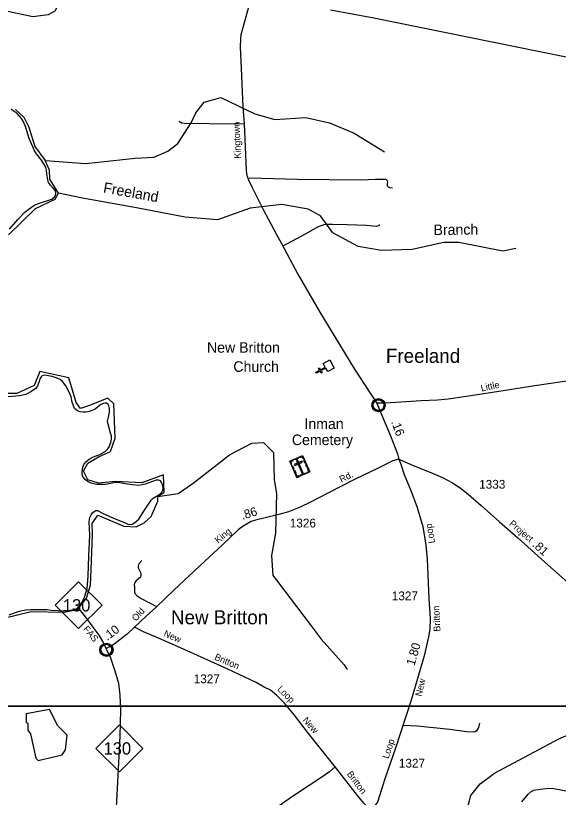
# Model space of a CAD drawing. Extents: x 2104537 to 2336408, y 34176 to 229611.
# Drawn here: x 2135938 to 2143655, y 123300 to 134413 of the extents above; entities that cross this region are included whole.
import ezdxf

# ---------------------------------------------------------------- set-up
doc = ezdxf.new("R2010")
doc.units = 0
for name, color, linetype in [('Exist Boundary Political CountyLine', 7, 'Continuous'), ('Exist Civil Demographics Community CELL', 7, 'Continuous'), ('Exist Civil Demographics Community Label', 7, 'Continuous'), ('Exist Cultural Cemetery CELL', 7, 'Continuous'), ('Exist Cultural Cemetery Label', 7, 'Continuous'), ('Exist Cultural Church CELL', 7, 'Continuous'), ('Exist Cultural Church with Cemetery Label', 7, 'Continuous'), ('Exist Hydrographic Creek Single Shore', 7, 'Continuous'), ('Exist Hydrographic Misc Water Feature', 7, 'Continuous'), ('Exist Hydrographic Pond Under 1500 Sq Ft', 7, 'Continuous'), ('Exist Hydrographic River Shore', 7, 'Continuous'), ('Exist Road Non-System Type 51', 7, 'Continuous'), ('Exist Road Primary NC Attributed', 7, 'Continuous'), ('Exist Road Primary NC Label', 7, 'Continuous'), ('Exist Road Primary NC Shield CELL', 7, 'Continuous'), ('Exist Road Primary NC Shield Number Label', 7, 'Continuous'), ('Exist Road Secondary Mileage Hundredths English Label', 7, 'Continuous'), ('Exist Road Secondary Type 51 Attributed', 7, 'Continuous'), ('Exist Road Secondary Type 51 Label', 7, 'Continuous'), ('Exist Road Secondary Type 51 Number Label', 7, 'Continuous'), ('Map Preparation Inset Cut Line', 7, 'Continuous'), ('Old_Level_32', 7, 'Continuous')]:
    doc.layers.add(name, color=color, linetype=linetype)

msp = doc.modelspace()

# ---------------------------------------------------------------- linework, layer by layer
at = {"layer": 'Exist Boundary Political CountyLine'}
for points in [[(2135850, 131375), (2135969, 131516), (2136070, 131621), (2136143, 131677), (2136198, 131712), (2136251, 131737), (2136318, 131760), (2136396, 131783), (2136455, 131805), (2136492, 131835), (2136508, 131868), (2136512, 131898), (2136505, 131924), (2136472, 131959), (2136434, 132001), (2136407, 132039), (2136394, 132079), (2136384, 132165), (2136379, 132215), (2136367, 132255), (2136346, 132298), (2136306, 132359), (2136235, 132446), (2136205, 132489), (2136182, 132549), (2136132, 132668), (2136082, 132824), (2136052, 132904), (2136022, 132950), (2135961, 133020), (2135875, 133080)], [(2136829, 126003), (2136882, 126073), (2136918, 126146), (2136953, 126268), (2136970, 126446), (2136978, 126732), (2136993, 127029), (2136986, 127220), (2136994, 127278), (2137013, 127318), (2137033, 127346), (2137056, 127364), (2137079, 127376), (2137104, 127377), (2137172, 127341), (2137329, 127271), (2137487, 127208), (2137535, 127186), (2137565, 127178), (2137597, 127182), (2137635, 127206), (2137689, 127255), (2137771, 127382), (2137829, 127470), (2137865, 127523), (2137895, 127555), (2137943, 127583), (2137988, 127610), (2138016, 127638), (2138031, 127665), (2138034, 127701), (2138026, 127749), (2138013, 127777), (2137996, 127799), (2137975, 127807), (2137938, 127811), (2137882, 127792), (2137781, 127753), (2137736, 127743), (2137683, 127734), (2137522, 127753), (2137389, 127774), (2137336, 127773), (2137215, 127749), (2137089, 127749), (2137011, 127768), (2136955, 127794), (2136926, 127817), (2136900, 127851), (2136885, 127890), (2136883, 127929), (2136893, 127993), (2136908, 128030), (2136938, 128068), (2136983, 128108), (2137044, 128143), (2137135, 128173), (2137212, 128219), (2137250, 128256), (2137268, 128284), (2137291, 128344), (2137301, 128392), (2137303, 128438), (2137288, 128478), (2137255, 128603), (2137245, 128649), (2137260, 128704), (2137273, 128777), (2137273, 128828), (2137263, 128868), (2137252, 128886), (2137230, 128903), (2137213, 128905), (2137188, 128901), (2137150, 128886), (2137067, 128818), (2137023, 128798), (2136983, 128785), (2136936, 128777), (2136897, 128775), (2136855, 128780), (2136825, 128790), (2136799, 128810), (2136775, 128830), (2136759, 128865), (2136744, 128918), (2136727, 128994), (2136693, 129071), (2136654, 129149), (2136606, 129210), (2136570, 129240), (2136513, 129263), (2136457, 129282), (2136377, 129297), (2136339, 129301), (2136314, 129292), (2136301, 129280), (2136284, 129250), (2136271, 129212), (2136248, 129149), (2136225, 129114)], [(2136225, 129114), (2136203, 129097), (2136153, 129064), (2136085, 129029), (2135991, 129008), (2135830, 128994)], [(2135848, 125897), (2135973, 125942), (2136030, 125958), (2136086, 125966), (2136150, 125969), (2136215, 125973), (2136313, 125973), (2136387, 125970), (2136444, 125963), (2136543, 125956), (2136623, 125950), (2136709, 125960), (2136790, 125976), (2136807, 125983), (2136829, 126003)]]:
    msp.add_lwpolyline(points, dxfattribs=at)
at = {"layer": 'Exist Civil Demographics Community CELL'}
for points in [[(2141021, 128887), (2141022, 128893), (2141023, 128899), (2141026, 128907), (2141029, 128912), (2141032, 128918), (2141036, 128923), (2141040, 128928), (2141045, 128932), (2141050, 128937), (2141056, 128940), (2141061, 128943), (2141066, 128946), (2141071, 128948), (2141077, 128950), (2141081, 128951), (2141086, 128952), (2141090, 128952), (2141096, 128953), (2141101, 128953), (2141107, 128952), (2141111, 128952), (2141116, 128951), (2141121, 128949), (2141127, 128947), (2141133, 128944), (2141139, 128941), (2141144, 128937), (2141150, 128933), (2141153, 128930), (2141157, 128926), (2141161, 128921), (2141164, 128916), (2141167, 128911), (2141170, 128906), (2141172, 128901), (2141173, 128896), (2141174, 128892), (2141176, 128886), (2141176, 128881), (2141176, 128875), (2141176, 128869), (2141176, 128863), (2141175, 128858), (2141173, 128852), (2141171, 128846), (2141169, 128841), (2141166, 128835), (2141163, 128830), (2141159, 128825), (2141155, 128820), (2141150, 128815), (2141145, 128811), (2141140, 128808), (2141135, 128805), (2141128, 128802), (2141121, 128799), (2141115, 128798), (2141109, 128796), (2141104, 128796), (2141100, 128796), (2141094, 128796), (2141090, 128796), (2141084, 128797), (2141078, 128798), (2141074, 128799), (2141069, 128801), (2141064, 128803), (2141060, 128806), (2141053, 128810), (2141048, 128814), (2141043, 128818), (2141038, 128823), (2141035, 128827), (2141032, 128831), (2141028, 128838), (2141026, 128842), (2141025, 128846), (2141022, 128854), (2141021, 128861), (2141020, 128866), (2141019, 128873), (2141019, 128877), (2141020, 128884)], [(2137151, 125411), (2137152, 125416), (2137154, 125423), (2137157, 125430), (2137160, 125436), (2137163, 125442), (2137167, 125447), (2137171, 125451), (2137175, 125456), (2137181, 125460), (2137186, 125464), (2137191, 125467), (2137196, 125469), (2137202, 125472), (2137207, 125473), (2137211, 125475), (2137216, 125475), (2137220, 125476), (2137227, 125476), (2137231, 125476), (2137237, 125476), (2137242, 125475), (2137247, 125474), (2137252, 125473), (2137257, 125471), (2137264, 125468), (2137270, 125464), (2137275, 125461), (2137280, 125457), (2137283, 125454), (2137287, 125449), (2137291, 125445), (2137294, 125440), (2137298, 125435), (2137300, 125430), (2137302, 125425), (2137304, 125420), (2137305, 125415), (2137306, 125409), (2137307, 125405), (2137307, 125399), (2137307, 125393), (2137306, 125387), (2137305, 125382), (2137304, 125375), (2137302, 125370), (2137299, 125365), (2137296, 125359), (2137293, 125353), (2137289, 125349), (2137285, 125344), (2137280, 125339), (2137275, 125335), (2137270, 125331), (2137266, 125329), (2137259, 125326), (2137252, 125323), (2137246, 125321), (2137239, 125320), (2137235, 125320), (2137230, 125319), (2137225, 125319), (2137220, 125320), (2137215, 125320), (2137209, 125322), (2137204, 125323), (2137199, 125325), (2137194, 125327), (2137190, 125329), (2137184, 125333), (2137178, 125338), (2137173, 125342), (2137169, 125347), (2137166, 125351), (2137163, 125355), (2137158, 125362), (2137157, 125366), (2137155, 125370), (2137152, 125378), (2137151, 125385), (2137150, 125390), (2137150, 125396), (2137150, 125401), (2137150, 125408)]]:
    msp.add_lwpolyline(points, close=True, dxfattribs=at)
for centre, radius in [((2141098, 128875), 94.3), ((2141098, 128875), 76.7), ((2137229, 125398), 94.3), ((2137228, 125399), 76.7)]:
    msp.add_circle(centre, radius, dxfattribs=at)
at = {"layer": 'Exist Cultural Cemetery CELL'}
for points in [[(2139835, 128079), (2140017, 128159), (2140120, 127926), (2139937, 127846)], [(2140035, 128119), (2140024, 128114), (2140012, 128144), (2139974, 128128), (2139970, 128138), (2140017, 128159)], [(2139853, 128039), (2139863, 128044), (2139850, 128073), (2139887, 128089), (2139883, 128100), (2139835, 128079)], [(2139900, 128033), (2139907, 128016), (2140015, 128063), (2140008, 128080)], [(2139903, 128108), (2139950, 128129), (2139955, 128119), (2139908, 128098)], [(2139947, 128096), (2139930, 128088), (2140011, 127902), (2140028, 127910)], [(2140054, 128048), (2140036, 128087), (2140047, 128092), (2140064, 128052)], [(2140080, 127987), (2140063, 128027), (2140073, 128031), (2140091, 127992)], [(2139882, 127971), (2139865, 128011), (2139875, 128015), (2139893, 127976)], [(2139909, 127910), (2139892, 127949), (2139902, 127954), (2139920, 127914)], [(2139985, 127879), (2140063, 127913), (2140068, 127903), (2139990, 127869)], [(2140089, 127912), (2140085, 127923), (2140105, 127932), (2140089, 127969), (2140099, 127973), (2140120, 127926)], [(2139968, 127859), (2139963, 127869), (2139943, 127861), (2139927, 127898), (2139917, 127893), (2139937, 127846)]]:
    msp.add_lwpolyline(points, close=True, dxfattribs=at)
at = {"layer": 'Exist Cultural Church CELL'}
msp.add_lwpolyline([(2140375, 129352), (2140348, 129402), (2140281, 129366), (2140296, 129338), (2140282, 129330), (2140267, 129358), (2140214, 129330), (2140206, 129344), (2140259, 129372), (2140244, 129401), (2140258, 129408), (2140273, 129380), (2140340, 129416), (2140313, 129467), (2140406, 129518), (2140468, 129403)], close=True, dxfattribs=at)
at = {"layer": 'Exist Hydrographic Creek Single Shore'}
msp.add_line((2139646, 126387), (2140124, 125757), dxfattribs=at)
for points in [[(2143050, 131101), (2142866, 131066), (2142240, 131189), (2142025, 131187), (2141574, 131087), (2141142, 131076), (2140808, 131132), (2140448, 131323), (2140273, 131566), (2140097, 131664), (2139722, 131727), (2139273, 131677), (2138806, 131509), (2138349, 131547), (2137656, 131679), (2136890, 131816), (2136546, 131891)], [(2137958, 127578), (2138248, 127622), (2138464, 127765), (2138979, 128169), (2139295, 128336), (2139462, 128343), (2139604, 128202), (2139615, 127812), (2139649, 127621), (2139634, 127054), (2139577, 126736), (2139595, 126454), (2139646, 126387)], [(2140124, 125757), (2140283, 125548), (2140609, 125184), (2140650, 125118)], [(2140161, 121072), (2140185, 121124), (2140426, 121359), (2140932, 121943), (2141163, 122161), (2142037, 122623), (2142185, 122742), (2142319, 122976), (2142409, 123325), (2142541, 123493), (2142749, 123643), (2143663, 124131), (2144179, 124357)]]:
    msp.add_lwpolyline(points, dxfattribs=at)
at = {"layer": 'Exist Hydrographic Misc Water Feature'}
msp.add_lwpolyline([(2136360, 132354), (2136935, 132312), (2137636, 132385), (2137903, 132402), (2138102, 132487), (2138244, 132596), (2138434, 132891), (2138499, 133031), (2138617, 133183), (2138857, 133250), (2139341, 133017), (2139625, 132936), (2140066, 132964), (2140400, 132889), (2140751, 132741), (2141185, 132476)], dxfattribs=at)
at = {"layer": 'Exist Hydrographic Pond Under 1500 Sq Ft'}
msp.add_lwpolyline([(2136257, 123822), (2136598, 123907), (2136648, 123975), (2136672, 124185), (2136539, 124315), (2136420, 124547), (2136087, 124488), (2136087, 124363), (2136113, 124356), (2136113, 124254), (2136148, 124205), (2136223, 123855), (2136257, 123822)], dxfattribs=at)
at = {"layer": 'Exist Hydrographic River Shore'}
for points in [[(2135860, 134889), (2135967, 134786), (2136117, 134769), (2136501, 134786), (2136557, 134729), (2136557, 134589), (2136494, 134474), (2136402, 134423), (2136185, 134395), (2135827, 134470)], [(2135936, 133079), (2136053, 132969), (2136127, 132828), (2136210, 132551), (2136360, 132354)], [(2136546, 131891), (2136424, 132086), (2136418, 132214), (2136360, 132354)], [(2135836, 131298), (2136222, 131670), (2136499, 131803), (2136546, 131891)], [(2137958, 127578), (2138051, 127641), (2138041, 127885), (2137734, 127771), (2137360, 127792), (2137114, 127765), (2136967, 127816), (2136902, 127938), (2136965, 128052), (2137118, 128141), (2137285, 128216), (2137352, 128408), (2137333, 128893), (2137248, 128977), (2136975, 128865), (2136862, 128830), (2136799, 128914), (2136694, 129265), (2136280, 129356), (2136203, 129153), (2135957, 129040), (2135718, 129040)], [(2135589, 125805), (2136157, 125940), (2136626, 125935), (2136819, 125969), (2136948, 126134), (2137004, 126318), (2137012, 126539), (2137032, 127043), (2137026, 127193), (2137106, 127314), (2137476, 127153), (2137651, 127145), (2137767, 127205), (2137866, 127295), (2137958, 127513), (2137958, 127578)]]:
    msp.add_lwpolyline(points, dxfattribs=at)
at = {"layer": 'Exist Road Non-System Type 51'}
msp.add_line((2141399, 128083), (2141385, 128119), dxfattribs=at)
for points in [[(2140415, 134493), (2141032, 134380), (2144398, 133701)], [(2139186, 132873), (2139050, 132868), (2138334, 132881), (2138296, 132883), (2138263, 132907)], [(2139260, 132105), (2139942, 132089), (2140848, 132081), (2141056, 132089), (2141198, 132090), (2141212, 132084), (2141218, 132074), (2141225, 132054), (2141219, 132018), (2141220, 132002), (2141225, 131990), (2141236, 131977), (2141253, 131969), (2141295, 131963)], [(2141110, 131443), (2141098, 131425), (2141066, 131415), (2140928, 131430), (2140650, 131440), (2140444, 131442), (2140360, 131445), (2140322, 131439), (2140232, 131404), (2140053, 131304), (2139749, 131142)], [(2137732, 126666), (2137694, 126625), (2137684, 126608), (2137680, 126589), (2137681, 126565), (2137689, 126543), (2137719, 126489), (2137719, 126461), (2137712, 126431), (2137652, 126377), (2137634, 126355), (2137625, 126327), (2137629, 126285), (2137626, 126231), (2137634, 126199), (2137668, 126167), (2137722, 126127), (2137941, 126011)], [(2142535, 124357), (2142518, 124293), (2142492, 124247), (2142472, 124233), (2142445, 124227), (2142350, 124230), (2142112, 124263), (2141648, 124313), (2141456, 124324)], [(2140483, 123732), (2140402, 123663), (2140278, 123578), (2140111, 123471), (2139875, 123313), (2139638, 123147), (2139625, 123105), (2139614, 122979), (2139593, 122876), (2139575, 122806), (2139566, 122736), (2139582, 122506)], [(2143137, 123235), (2143224, 123346), (2143268, 123384), (2143304, 123404), (2143395, 123417), (2143485, 123426), (2143567, 123431), (2143936, 123362), (2143990, 123362), (2144022, 123384), (2144051, 123423), (2144085, 123451), (2144137, 123469), (2144195, 123510), (2144238, 123554)]]:
    msp.add_lwpolyline(points, dxfattribs=at)
at = {"layer": 'Exist Road Primary NC Attributed'}
for points in [[(2137226, 125416), (2137176, 125518), (2137124, 125606), (2137056, 125702), (2136952, 125844), (2136885, 125928), (2136826, 126000)], [(2137364, 122982), (2137388, 123426), (2137404, 123796), (2137425, 124170), (2137435, 124541), (2137425, 124752), (2137405, 124919), (2137355, 125095), (2137290, 125280), (2137226, 125416)]]:
    msp.add_lwpolyline(points, dxfattribs=at)
at = {"layer": 'Exist Road Primary NC Shield CELL'}
for points in [[(2136501, 126032), (2136834, 126365), (2137167, 126032), (2136834, 125699)], [(2137080, 123997), (2137413, 124330), (2137746, 123997), (2137413, 123665)]]:
    msp.add_lwpolyline(points, close=True, dxfattribs=at)
at = {"layer": 'Exist Road Secondary Type 51 Attributed'}
for points in [[(2139305, 134740), (2139141, 134142), (2139134, 134090), (2139132, 133966), (2139143, 133665), (2139167, 133118), (2139186, 132873), (2139198, 132657), (2139217, 132212), (2139227, 132142), (2139249, 132081), (2139290, 131990), (2139457, 131656), (2139648, 131301), (2139716, 131174), (2139949, 130738), (2140265, 130199), (2140754, 129389), (2140978, 129045), (2141072, 128903)], [(2149050, 129307), (2148547, 129250), (2147740, 129164), (2147185, 129103), (2146904, 129070), (2146733, 129058), (2146620, 129049), (2146505, 129049), (2145518, 129135), (2144807, 129192), (2144286, 129237), (2144116, 129246), (2144040, 129246), (2143947, 129239), (2143710, 129207), (2143320, 129149), (2142778, 129063), (2142318, 128993), (2142090, 128959), (2141937, 128948), (2141706, 128936), (2141345, 128914), (2141183, 128903), (2141072, 128903)], [(2141072, 128903), (2141156, 128711), (2141266, 128440), (2141366, 128183), (2141388, 128108)], [(2141388, 128108), (2141303, 128084), (2141095, 127982), (2140768, 127823), (2140386, 127629), (2140132, 127496), (2139983, 127426), (2139818, 127359), (2139681, 127322), (2139487, 127276), (2139347, 127243), (2139285, 127221), (2139231, 127189), (2139173, 127153), (2139103, 127102), (2138879, 126892), (2138628, 126660), (2138188, 126247), (2137939, 126010), (2137787, 125870), (2137626, 125718)], [(2141388, 128108), (2141414, 128039), (2141463, 127889), (2141567, 127641), (2141646, 127420), (2141729, 127150), (2141770, 126884), (2141788, 126688), (2141813, 126122), (2141831, 125844), (2141826, 125691), (2141810, 125580), (2141745, 125314), (2141560, 124684), (2141339, 124000), (2141190, 123562), (2141165, 123488)], [(2141388, 128108), (2141591, 128018), (2141840, 127917), (2142009, 127847), (2142152, 127772), (2142260, 127699), (2142371, 127612), (2142555, 127450), (2142818, 127218), (2143079, 126989), (2143463, 126643), (2143999, 126170), (2144422, 125802), (2144574, 125664)], [(2137626, 125718), (2137522, 125619), (2137337, 125479), (2137292, 125449), (2137226, 125416)], [(2141165, 123488), (2141084, 123232), (2141050, 123191), (2141028, 123167), (2140996, 123150), (2140968, 123152), (2140932, 123176), (2140889, 123219), (2140801, 123327), (2140483, 123732), (2140103, 124206), (2139903, 124467), (2139759, 124639), (2139650, 124749), (2139560, 124822), (2139474, 124869), (2139359, 124934), (2138955, 125124), (2138281, 125424), (2137971, 125564), (2137755, 125655), (2137626, 125718)]]:
    msp.add_lwpolyline(points, dxfattribs=at)
at = {"layer": 'Map Preparation Inset Cut Line'}
for points in [[(2165966, 124595), (2135584, 124595), (2135584, 153500), (2165966, 153500)], [(2163450, 80447), (2123592, 80447), (2123592, 124595), (2166610, 124595), (2166610, 99632), (2163450, 99632)]]:
    msp.add_lwpolyline(points, close=True, dxfattribs=at)

# ---------------------------------------------------------------- texts
at = {"layer": 'Exist Civil Demographics Community Label'}
for s, p in [('Freeland', (2141203, 129477)), ('New Britton', (2138147, 125760))]:
    msp.add_text(s, height=200, dxfattribs=at).set_placement(p)
at = {"layer": 'Exist Cultural Cemetery Label'}
for s, p in [('Inman', (2140045, 128536)), ('Cemetery', (2139866, 128308))]:
    msp.add_text(s, height=150, dxfattribs=at).set_placement(p)
at = {"layer": 'Exist Cultural Church with Cemetery Label'}
for s, p in [('New Britton', (2138659, 129621)), ('Church', (2139034, 129349))]:
    msp.add_text(s, height=150, dxfattribs=at).set_placement(p)
at = {"layer": 'Exist Road Primary NC Label'}
msp.add_text('FAS', height=95, rotation=309.7975, dxfattribs=at).set_placement((2136892, 125690))
at = {"layer": 'Exist Road Primary NC Shield Number Label'}
for p in [(2136610, 125943), (2137189, 123908)]:
    msp.add_text('130', height=175, dxfattribs=at).set_placement(p)
at = {"layer": 'Exist Road Secondary Mileage Hundredths English Label'}
for s, rotation, p in [('.16', 291.0962, (2141274, 128639)), ('.86', 17.108, (2139163, 127245)), ('.81', 318.0198, (2143274, 126880)), ('.10', 37.1052, (2137241, 125522)), ('1.80', 73.6288, (2141608, 125163))]:
    msp.add_text(s, height=125, rotation=rotation, dxfattribs=at).set_placement(p)
at = {"layer": 'Exist Road Secondary Type 51 Label'}
for s, rotation, p in [('Kingtown', 92.2111, (2139142, 132382)), ('Little', 12.1743, (2142563, 129068)), ('Rd.', 26.1537, (2140570, 127772)), ('Project', 319.3885, (2142948, 127178)), ('Loop', 99.8046, (2141902, 126919)), ('King', 39.5476, (2138818, 126905)), ('Old', 47.9405, (2137650, 125796)), ('Britton', 92.684, (2141978, 125659)), ('New', 336.6265, (2138034, 125595)), ('Britton', 336.8502, (2138757, 125262)), ('New', 77.3813, (2141710, 124728)), ('Loop', 314.9932, (2139651, 124831)), ('New', 311.3251, (2140012, 124391)), ('Loop', 71.4886, (2141239, 123843)), ('Britton', 306.9018, (2140642, 123631))]:
    msp.add_text(s, height=95, rotation=rotation, dxfattribs=at).set_placement(p)
at = {"layer": 'Exist Road Secondary Type 51 Number Label'}
for s, p in [('1333', (2142529, 127688)), ('1326', (2139836, 127137)), ('1327', (2141287, 126102)), ('1327', (2138470, 124923)), ('1327', (2141387, 123724))]:
    msp.add_text(s, height=125, dxfattribs=at).set_placement(p)
at = {"layer": 'Old_Level_32'}
for s, rotation, p in [('Freeland ', 349.8836, (2137176, 131899)), ('Branch', 0.6292, (2141881, 131293))]:
    msp.add_text(s, height=150, rotation=rotation, dxfattribs=at).set_placement(p)

doc.saveas('drawing.dxf')
